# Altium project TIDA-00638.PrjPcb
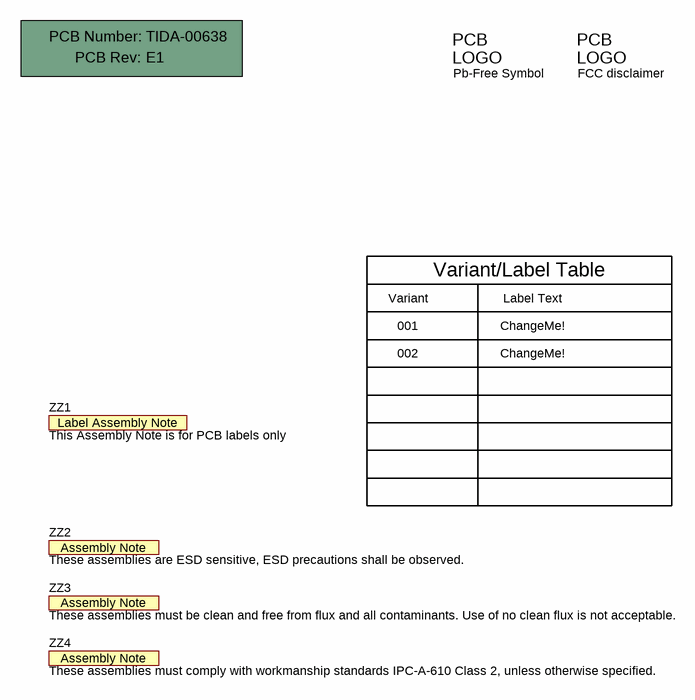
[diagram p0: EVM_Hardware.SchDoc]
Orderable: No; TID: TIDA-00638; TechSupport: http://www.ti.com/support; SCH_Rev: E1; PRJ_Title: ISO Gate Driver Card; PRJ_Number: TIDA-00638; PRJ_Engineer: Bart Basile; PRJ_Customer: Public Release; PCB_Rev: E1; PCB_Layout: Bart Basile; CopyrightYear: 2017
2 sheets, 40 parts. Net scope: global (net labels, ports and power ports of the same name join across sheets).
Board file: TIDA-00638Pcb.PcbDoc
Sheets:
  EVM_Hardware.SchDoc
  TIDA-00638Sch.SchDoc

## Sheet EVM_Hardware.SchDoc
size 431 x 279 mm; Date: Not shown in title block; ApprovedBy: Not shown in title block; CheckedBy: Not shown in title block; Author: Not shown in title block; CompanyName: Not shown in title block; Engineer: Not shown in title block; Organization: Not shown in title block; Address1: Not shown in title block; Address2: Not shown in title block; Address3: Not shown in title block; Address4: Not shown in title block; DocumentNumber: 1; Revision: Use project parameter SCH_Rev; SheetNumber: 3; SheetTotal: 3; PageSetup: Record=PageOptions¦CenterHorizontal=True¦CenterVertical=True¦PrintScale=1.00¦XCorrection=1.00¦YCorrection=1.00¦PrintKind=0¦BorderSize=5000000¦LeftOffset=0¦BottomOffset=0¦Orientation=2¦PaperLength=1000¦PaperWidth=1000¦Scale=100¦PaperSource=15¦PrintQuality=600¦MediaType=1¦DitherType=10¦PaperKind=Letter¦PrintScaleMode=1

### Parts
!PCB1  Printed Circuit Board  (value not drawn)  (mechanical)
Logo2  Pb-Free Symbol  [Pb-Free_Overlay_Small]  (no BOM)
Logo3  FCC disclaimer  [FCC_disclaimer]  (no BOM)
ZZ1  This Assembly Note is for PCB labels only  [AssemblyNoteLabel]  (no BOM)
ZZ2  These assemblies are ESD sensitive, ESD precautions shall be observed.  [AssemblyNote]  (no BOM)
ZZ3  These assemblies must be clean and free from flux and all contaminants. Use of no clean flux is not acceptable.  [AssemblyNote]  (no BOM)
ZZ4  These assemblies must comply with workmanship standards IPC-A-610 Class 2, unless otherwise specified.  [AssemblyNote]  (no BOM)

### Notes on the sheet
- Variant
- Variant/Label Table
- Label Text
- 001
- 002
- ChangeMe!

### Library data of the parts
!PCB1 = PCB: Manufacturer: Any; PartNumber: TIDA-00638; SymbolCreator: a0412235
Logo2 = Pb-Free: SymbolCreator: a0412235
Logo3 = FCC_disclaimer: SymbolCreator: codlsc
ZZ1 = AssemblyNoteLabel: SymbolCreator: a0412235
ZZ2-ZZ4 = AssemblyNote: SymbolCreator: codlsc

## Sheet TIDA-00638Sch.SchDoc
size 431 x 279 mm; Date: Not shown in title block; ApprovedBy: Not shown in title block; CheckedBy: Not shown in title block; Author: Not shown in title block; CompanyName: Not shown in title block; Engineer: Not shown in title block; Organization: Not shown in title block; Address1: Not shown in title block; Address2: Not shown in title block; Address3: Not shown in title block; Address4: Not shown in title block; DocumentNumber: 1; Revision: Use project parameter SCH_Rev; SheetNumber: 2; SheetTotal: 3; PageSetup: Record=PageOptions¦CenterHorizontal=True¦CenterVertical=True¦PrintScale=1.00¦XCorrection=1.00¦YCorrection=1.00¦PrintKind=0¦BorderSize=5000000¦LeftOffset=0¦BottomOffset=0¦Orientation=2¦PaperLength=1000¦PaperWidth=1000¦Scale=100¦PaperSource=15¦PrintQuality=600¦MediaType=1¦DitherType=10¦PaperKind=Letter¦PrintScaleMode=1
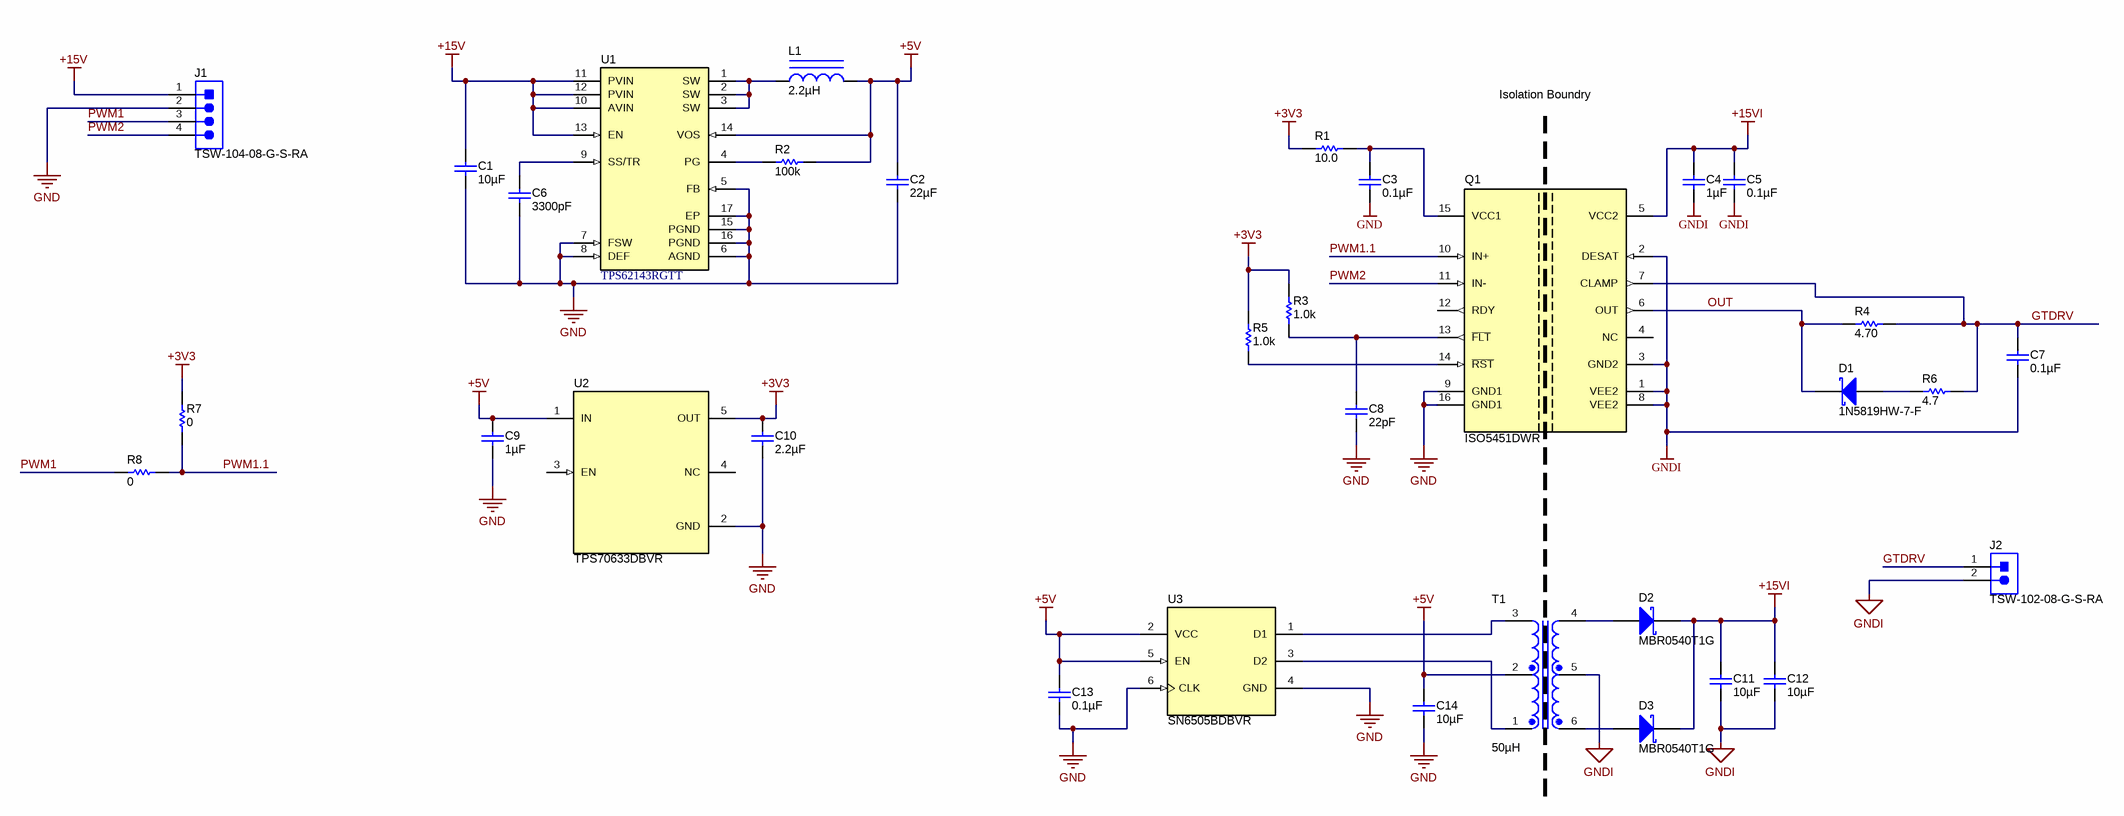
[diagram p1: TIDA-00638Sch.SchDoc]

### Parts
C1  ValueDisplayed: 10µF  [0805_HV]  (hidden comment: GRM219R61E106KA12D)
C2  ValueDisplayed: 22µF  [1206_180]  (hidden comment: GRM31CR61A226KE19L)
C3  ValueDisplayed: 0.1µF  [0603]  (hidden comment: C1608X7R1H104K080AA)
C4  ValueDisplayed: 1µF  [0603]  (hidden comment: C1608X7R1V105K080AC)
C5  ValueDisplayed: 0.1µF  [0603]  (hidden comment: C1608X7R1H104K080AA)
C6  ValueDisplayed: 3300pF  [0603]  (hidden comment: GRM188R71E332KA01D)
C7  ValueDisplayed: 0.1µF  [0603]  (hidden comment: GRM188R71H104KA93D)
C8  ValueDisplayed: 22pF  [0603]  (hidden comment: 06035A220JAT2A)
C9  ValueDisplayed: 1µF  [0603]  (hidden comment: CL10B105KQ8NNNC)
C10  ValueDisplayed: 2.2µF  [0402]  (hidden comment: CL05A225KQ5NNNC)
C11  ValueDisplayed: 10µF  [0805_HV]  (hidden comment: GRM21BR6YA106KE43L)
C12  ValueDisplayed: 10µF  [0805_HV]  (hidden comment: GRM21BR6YA106KE43L)
C13  ValueDisplayed: 0.1µF  [0603]  (hidden comment: GRM188R71H104KA93D)
C14  ValueDisplayed: 10µF  [0603]  (hidden comment: C1608X5R1A106M080AC)
D1  1N5819HW-7-F  [SOD-123]
D2  MBR0540T1G  [SOD-123]
D3  MBR0540T1G  [SOD-123]
J1  TSW-104-08-G-S-RA  [TSW-104-08-G-S-RA]
J2  TSW-102-08-G-S-RA  [TSW-102-08-G-S-RA]
L1  ValueDisplayed: 2.2µH  [SDR0403]  (hidden comment: SDR0403-2R2ML)
Q1  ISO5451DWR  [DW0016B_N]
R1  ValueDisplayed: 10.0  [0603]  (hidden comment: RC0603FR-0710RL)
R2  ValueDisplayed: 100k  [0603]  (hidden comment: CRCW0603100KJNEA)
R3  ValueDisplayed: 1.0k  [0603]  (hidden comment: CRCW06031K00JNEA)
R4  ValueDisplayed: 4.70  [1206]  (hidden comment: RC1206FR-074R7L)
R5  ValueDisplayed: 1.0k  [0603]  (hidden comment: CRCW06031K00JNEA)
R6  ValueDisplayed: 4.7  [0805_HV]  (hidden comment: RC0805JR-074R7L)
R7  ValueDisplayed: 0  [0603]  (hidden comment: CRCW06030000Z0EA)
R8  ValueDisplayed: 0  [0603]  (hidden comment: CRCW06030000Z0EA)
T1  ValueDisplayed: 50µH  [Wurth_750342879]  (hidden comment: 750342879)
U1  TPS62143RGTT  [RGT0016C]
U2  TPS70633DBVR  [DBV0005A_N]
U3  SN6505BDBVR  [DBV0006A_N]

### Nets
+3V3: C10.1 R1.1 R3.2 R5.2 R7.2 U2.5(OUT)
+5V: C2.1 C9.1 C13.1 C14.1 L1.2 R2.2 T1.2 U1.14(VOS) U2.1(IN) U3.2(VCC) U3.5(EN)
+15V: C1.1 J1.1 U1.10(AVIN) U1.11(PVIN) U1.12(PVIN) U1.13(EN)
+15VI: C4.1 C5.1 C11.1 C12.1 D2.1(K) D3.1(K) Q1.5(VCC2)
GND: C1.2 C2.2 C3.2 C6.2 C8.2 C9.2 C10.2 C13.2 C14.2 J1.2 Q1.9(GND1) Q1.16(GND1) U1.5(FB) U1.6(AGND) U1.7(FSW) U1.8(DEF) U1.15(PGND) U1.16(PGND) U1.17(EP) U2.2(GND) U3.4(GND) U3.6(CLK)
GNDI: C4.2 C5.2 C7.2 C11.2 C12.2 J2.2 Q1.1(VEE2) Q1.2(DESAT) Q1.3(GND2) Q1.8(VEE2) T1.5
GTDRV: C7.1 J2.1 Q1.7(CLAMP) R4.2 R6.2
OUT: D1.1(K) Q1.6(OUT) R4.1
PWM1: J1.3 R8.1
PWM1.1: Q1.10(IN+) R7.1 R8.2
PWM2: J1.4 Q1.11(IN-)
NetC3_1: C3.1 Q1.15(VCC1) R1.2
NetC6_1: C6.1 U1.9(SS/TR)
NetC8_1: C8.1 Q1.13(~{FLT}) R3.1
NetD1_2: D1.2(A) R6.1
NetD2_2: D2.2(A) T1.4
NetD3_2: D3.2(A) T1.6
NetL1_1: L1.1 U1.1(SW) U1.2(SW) U1.3(SW)
NetQ1_14: Q1.14(~{RST}) R5.1
NetR2_1: R2.1 U1.4(PG)
NetT1_1: T1.1 U3.3(D2)
NetT1_3: T1.3 U3.1(D1)

Not connected (* = marked no-connect by the designer): Q1 4(NC) 12(RDY); U2 3(EN) 4(NC)

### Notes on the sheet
- Isolation Boundry

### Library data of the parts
C1 = GRM219R61E106KA12D: CAP, CERM, 10 µF, 25 V, +/- 10%, X5R, 0805; Manufacturer: MuRata; Polarized: N; CompType: Capacitor; Value: 10uF; U/M: EA; Cap_F: 0.00001; Tolerance_%: 10; Value1: Unknown; VDC_V: 25; Value2: 25V; TaMin_C: -55; TaMax_C: 85; Cap_Case: 0805; SizeArea_mm2: 2.5; SizeAreaWB_mm2: 6.75; SizeX_mm: 2; SizeY_mm: 1.25; SizeZ_mm: 1.45; AEC Category: Q200
C2 = GRM31CR61A226KE19L: CAP, CERM, 22 µF, 10 V, +/- 10%, X5R, 1206; Manufacturer: MuRata; Polarized: N; CompType: Capacitor; Value: 22uF; U/M: EA; Cap_F: 0.000022; Tolerance_%: 10; Value1: Unknown; Value2: 10V; TaMin_C: -55; TaMax_C: 85; Cap_Case: 1206; SizeArea_mm2: 5.12; SizeAreaWB_mm2: 10.92; SizeX_mm: 3.2; SizeY_mm: 1.6; SizeZ_mm: 1.8; AEC Category: Q200
C3 C5 = C1608X7R1H104K080AA: CAP, CERM, 0.1 µF, 50 V, +/- 10%, X7R, 0603; Manufacturer: TDK; Polarized: N; CompType: Capacitor; Value: 0.1uF; U/M: EA; Cap_F: 0.0000001; Tolerance_%: 10; ESR_ohm: 0.0296; Value1: 0.0296 ohm; VDC_V: 50; Value2: 50V; IRMS_A: 0.97199; TaMin_C: -55; TaMax_C: 125; SizeArea_mm2: 1.28; SizeAreaWB_mm2: 4.68; SizeX_mm: 1.6; SizeY_mm: 0.8; SizeZ_mm: 1; AEC Category: Q200
C4 = C1608X7R1V105K080AC: CAP, CERM, 1 µF, 35 V, +/- 10%, X7R, 0603; Manufacturer: TDK; Polarized: N; CompType: Capacitor; Value: 1uF; U/M: EA; Cap_F: 0.000001; Tolerance_%: 10; Value1: Unknown; VDC_V: 35; Value2: 35V; TaMin_C: -55; TaMax_C: 125; SizeArea_mm2: 1.28; SizeAreaWB_mm2: 4.68; SizeX_mm: 1.6; SizeY_mm: 0.8; SizeZ_mm: 1; AEC Category: Q200
C6 = GRM188R71E332KA01D: CAP, CERM, 3300 pF, 25 V, +/- 10%, X7R, 0603; Manufacturer: MuRata; Polarized: N; CompType: Capacitor; Value: 3300pF; U/M: EA; Cap_F: 0.0000000033; Tolerance_%: 10; Value1: Unknown; VDC_V: 25; Value2: 25V; TaMin_C: -55; TaMax_C: 125; SizeArea_mm2: 1.28; SizeAreaWB_mm2: 4.68; SizeX_mm: 1.6; SizeY_mm: 0.8; SizeZ_mm: 1; AEC Category: Q200
C7 C13 = GRM188R71H104KA93D: CAP, CERM, 0.1 µF, 50 V, +/- 10%, X7R, 0603; Manufacturer: MuRata; Polarized: N; CompType: Capacitor; Value: 0.1uF; U/M: EA; Cap_F: 0.0000001; Tolerance_%: 10; Value1: Unknown; VDC_V: 50; Value2: 50V; TaMin_C: -55; TaMax_C: 125; SizeArea_mm2: 1.28; SizeAreaWB_mm2: 4.68; SizeX_mm: 1.6; SizeY_mm: 0.8; SizeZ_mm: 1; AEC Category: Q200
C8 = 06035A220JAT2A: CAP, CERM, 22 pF, 50 V, +/- 5%, C0G/NP0, 0603; Manufacturer: AVX; Polarized: N; CompType: Capacitor; Value: 22pF; U/M: EA; Cap_F: 0.000000000022; Tolerance_%: 5; ESR_ohm: 0.259; Value1: 0.259 ohm; VDC_V: 50; Value2: 50V; TaMin_C: -55; TaMax_C: 125; SizeArea_mm2: 1.28; SizeAreaWB_mm2: 4.68; SizeX_mm: 1.6; SizeY_mm: 0.8; SizeZ_mm: 1; AEC Category: Q200
C9 = CL10B105KQ8NNNC: CAP, CERM, 1 µF, 6.3 V, +/- 10%, X7R, 0603; Manufacturer: Samsung Electro-Mechanics; Polarized: N; CompType: Capacitor; Value: 1uF; U/M: EA; Cap_F: 0.000001; Tolerance_%: 10; Value1: Unknown; VDC_V: 6.3; Value2: 6.3V; TaMin_C: -55; TaMax_C: 125; SizeArea_mm2: 1.28; SizeAreaWB_mm2: 4.68; SizeX_mm: 1.6; SizeY_mm: 0.8; SizeZ_mm: 1; AEC Category: Q200
C10 = CL05A225KQ5NNNC: CAP, CERM, 2.2 µF, 6.3 V, +/- 10%, X5R, 0402; Manufacturer: Samsung; Polarized: N; CompType: Capacitor; Value: 2.2uF; U/M: EA; Cap_F: 0.0000022; Tolerance_%: 10; Value1: Unknown; VDC_V: 6.3; Value2: 6.3V; TaMin_C: -55; TaMax_C: 85; SizeArea_mm2: 0.5; SizeAreaWB_mm2: 3; SizeX_mm: 1; SizeZ_mm: 0.6; AEC Category: Q200
C11 C12 = GRM21BR6YA106KE43L: CAP, CERM, 10 µF, 35 V, +/- 10%, X5R, 0805; Manufacturer: MuRata; Polarized: N; CompType: Capacitor; Value: 10uF; U/M: EA; Cap_F: 0.00001; Tolerance_%: 10; Value1: Unknown; VDC_V: 35; Value2: 35V; TaMin_C: -55; TaMax_C: 85; Cap_Case: 0805; SizeArea_mm2: 2.5; SizeAreaWB_mm2: 6.75; SizeX_mm: 2; SizeY_mm: 1.25; SizeZ_mm: 1.45; AEC Category: Q200
C14 = C1608X5R1A106M080AC: CAP, CERM, 10 µF, 10 V, +/- 20%, X5R, 0603; Manufacturer: TDK; Polarized: N; CompType: Capacitor; Value: 10uF; U/M: EA; Cap_F: 0.00001; Tolerance_%: 20; ESR_ohm: 0.0078; Value1: 0.0078 ohm; VDC_V: 10; Value2: 10V; IRMS_A: 1.85; TaMin_C: -55; TaMax_C: 85; SizeArea_mm2: 1.28; SizeAreaWB_mm2: 4.68; SizeX_mm: 1.6; SizeY_mm: 0.8; SizeZ_mm: 1; AEC Category: Q200
D1 = 1N5819HW-7-F: Diode, Schottky, 40 V, 1 A, SOD-123; Manufacturer: Diodes Inc.; U/M: EA; Vf_V: 0.45; Value: 40V; Value1: 1A; Value2: 0.45V; Io_A: 1; Vr_V: 40; TJmax_C: 125; SizeAreaWB_mm2: 13.095; SizeArea_mm2: 6.545; SizeX_mm: 3.85; SizeY_mm: 1.7; SizeZ_mm: 1.35; AEC Category: Q101
D2 D3 = MBR0540T1G: Diode, Schottky, 40 V, 0.5 A, SOD-123; Manufacturer: ON Semiconductor; U/M: EA; Vf_V: 0.51; Value: 40V; Value1: 0.5A; Value2: 0.51V; Io_A: 0.5; Vr_V: 40; TJmax_C: 150; RJC_CperW: 118; SizeAreaWB_mm2: 13.095; SizeArea_mm2: 6.545; SizeX_mm: 3.85; SizeY_mm: 1.7; SizeZ_mm: 1.35; AEC Category: Q101
J1 = TSW-104-08-G-S-RA: Header, 100mil, 4x1, Gold, R/A, TH; Manufacturer: Samtec; SymbolCreator: a0412235; Pitch_mm: 2.54; Gender: Male; Shrouded: N; Row_Count: 1; Current_A: 6.3; Voltage_V: 550; Cert_CSA: Y
J2 = TSW-102-08-G-S-RA: Header, 100mil, 2x1, Gold, R/A, TH; Manufacturer: Samtec; SymbolCreator: a0412235; Pitch_mm: 2.54; Gender: Male; Shrouded: N; Row_Count: 1; Current_A: 6.3; Voltage_V: 550; Cert_CSA: Y
L1 = SDR0403-2R2ML: Inductor, Drum Core, Ferrite, 2.2 µH, 2.6 A, 0.047 ohm, SMD; Manufacturer: Bourns; Value: 2.2uH; Ind_H: 2.2E-6; Imax_A: 2.6; Irms: 2.6A @ 40C rise; Isat: 3.77A @ 10% inductance drop; DCR_ohm: 0.047; Value2: 2.6A; SizeAreaWB_mm2: 27.5; SizeArea_mm2: 18; SizeX_mm: 4.5; SizeY_mm: 4; SizeZ_mm: 3.2; AEC Category: Q200
Q1 = ISO5451DWR: High-CMTI 2.5-A / 5-A Isolated IGBT, MOSFET Gate Driver with Active Safety Features, DW0016B (SOIC-16); Manufacturer: Texas Instruments; SymbolCreator: Altium; SizeArea_mm2: 107.12; SizeAreaWB_mm2: 152.52; SizeX_mm: 10.4; SizeY_mm: 10.3; SizeZ_mm: 2.65; CompType: IC; U/M: EA
R1 = RC0603FR-0710RL: RES, 10.0, 1%, 0.1 W, 0603; Manufacturer: Yageo America; CompType: Resistor; Value: 10.0; Res_ohm: 10; Value_Code: 10R0; Tolerance_%: 1; Power_W: 0.1; Value2: 0.1W; VDC_V: 150; TempCo: 200 ppm/C; SizeArea_mm2: 1.28; SizeX_mm: 1.6; SizeY_mm: 0.8; EIA_Code: E96; U/M: EA; AEC Category: Q200
R2 = CRCW0603100KJNEA: RES, 100 k, 5%, 0.1 W, 0603; Manufacturer: Vishay-Dale; CompType: Resistor; Value: 100k; Res_ohm: 100000; Tolerance_%: 5; Power_W: 0.1; Value2: 0.1W; VDC_V: 75; TempCo: 200 ppm/C; SizeArea_mm2: 1.28; SizeX_mm: 1.6; SizeY_mm: 0.8; SizeZ_mm: 1; EIA_Code: E24; U/M: EA; AEC Category: Q200
R3 R5 = CRCW06031K00JNEA: RES, 1.0 k, 5%, 0.1 W, 0603; Manufacturer: Vishay-Dale; CompType: Resistor; Value: 1.0k; Res_ohm: 1000; Value_Code: 1k00; Tolerance_%: 5; Power_W: 0.1; Value2: 0.1W; VDC_V: 75; TempCo: 200 ppm/C; SizeArea_mm2: 1.28; SizeX_mm: 1.6; SizeY_mm: 0.8; SizeZ_mm: 1; EIA_Code: E24; U/M: EA; AEC Category: Q200
R4 = RC1206FR-074R7L: RES, 4.70, 1%, 0.25 W, 1206; Manufacturer: Yageo America; CompType: Resistor; Value: 4.70; Res_ohm: 4.7; Value_Code: 4R70; Tolerance_%: 1; Power_W: 0.25; Value2: 0.25W; VDC_V: 200; TempCo: 200 ppm/C; SizeArea_mm2: 5.12; SizeX_mm: 3.2; SizeY_mm: 1.6; SizeZ_mm: 1.35; U/M: EA; AEC Category: Q200
R6 = RC0805JR-074R7L: RES, 4.7, 5%, 0.125 W, 0805; Manufacturer: Yageo America; CompType: Resistor; Value: 4.7; Value_Code: 4R70; Tolerance_%: 5; Power_W: 0.125; Value2: 0.125W; VDC_V: 150; TempCo: 200 ppm/C; SizeArea_mm2: 2.5; SizeX_mm: 2; SizeY_mm: 1.25; SizeZ_mm: 1.45; EIA_Code: E24; U/M: EA; AEC Category: Q200
R7 R8 = CRCW06030000Z0EA: RES, 0, 5%, 0.1 W, 0603; Manufacturer: Vishay-Dale; CompType: Resistor; Value: 0; Value_Code: 0000; Tolerance_%: 5; Power_W: 0.1; Value2: 0.1W; VDC_V: 75; TempCo: 200 ppm/C; SizeArea_mm2: 1.28; SizeX_mm: 1.6; SizeY_mm: 0.8; SizeZ_mm: 1; EIA_Code: E24; U/M: EA; AEC Category: Q200
T1 = 750342879: Transformer, 50 uH, SMT; Manufacturer: Wurth Elektronik; SymbolCreator: Altium; Value: 50uH; Lp: 50
U1 = TPS62143RGTT: Buck Step Down Regulator with 3 to 17 V Input and 5 V Output, -40 to 85 degC, 16-Pin QFN (RGT), Green (RoHS & no Sb/Br); Manufacturer: Texas Instruments; Alternate PartNumber: Equivalent; Duty Cycle(Max)(%): 100; Iout(Max)(A): 2; Iq(Typ)(mA): 0.017; Preset Vout(V): 5; Rating: Catalog; Regulated Outputs(#): 1; SubFamily: Step-Down Regulator; Switch Current Limit(Typ)(A): 3; Synchronous Rectification: TRUE; Vin(Max)(V): 17
U2 = TPS70633DBVR: 150-mA, 6.5-V, 1-uA IQ Voltage Regulators with Enable, DBV0005A (SOT-5); Alternate PartNumber: TPS70633DBVT; Manufacturer: Texas Instruments; SymbolCreator: Altium; SizeArea_mm2: 8.12; SizeAreaWB_mm2: 14.82; SizeX_mm: 2.8; SizeY_mm: 2.9; SizeZ_mm: 1.45; CompType: IC; U/M: EA
U3 = SN6505BDBVR: Low-Noise 1 A, 420 kHz Transformer Driver, DBV0006A (SOT-23-6); Alternate PartNumber: SN6505BDBVT; Manufacturer: Texas Instruments; SymbolCreator: Altium; SizeArea_mm2: 8.12; SizeAreaWB_mm2: 14.82; SizeX_mm: 2.8; SizeY_mm: 2.9; SizeZ_mm: 1.45; CompType: IC; U/M: EA; Green_Lifecycle: Active; Green_REACh: Passed

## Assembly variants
001: not fitted C7 R8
